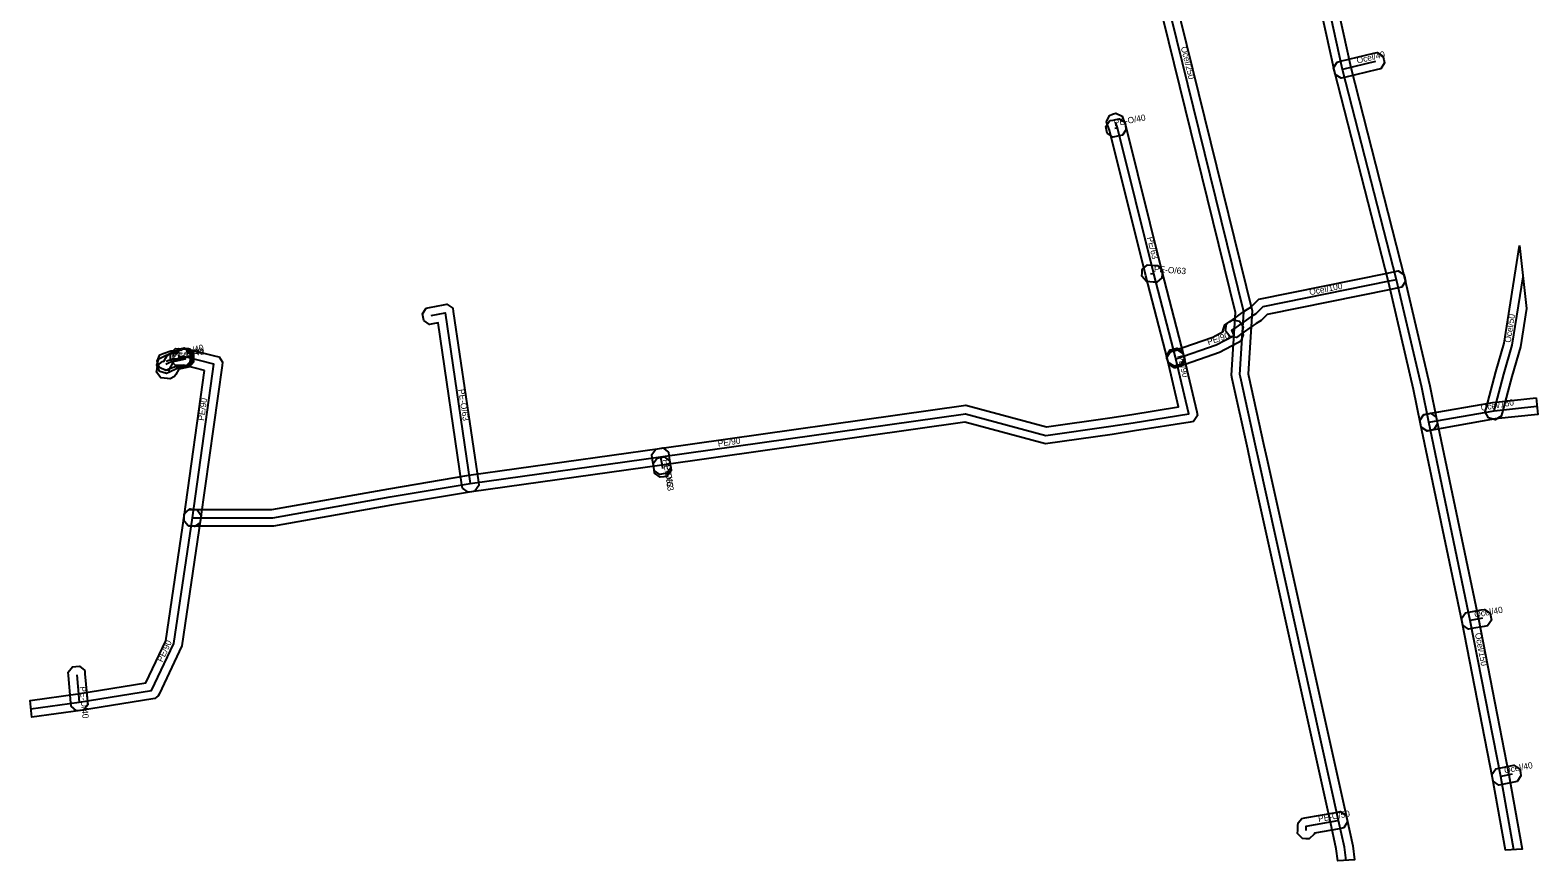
# Model space of a CAD drawing. Extents: x -697438 to -697243, y -1038718 to -1038521.
# Drawn here: x -697423.8 to -697243.1, y -1038717.8 to -1038618.2 of the extents above; entities that cross this region are included whole.
import ezdxf

# ---------------------------------------------------------------- set-up
doc = ezdxf.new("R2010")
doc.units = 0
for name, color, linetype in [('1', 7, 'Continuous'), ('14', 7, 'Continuous'), ('20', 7, 'Continuous'), ('24', 7, 'Continuous'), ('30', 7, 'Continuous')]:
    doc.layers.add(name, color=color, linetype=linetype)

msp = doc.modelspace()

# ---------------------------------------------------------------- linework, layer by layer
at = {"layer": '1'}
for points in [[(-697277.05, -1038570.41), (-697265.56, -1038622.68), (-697259.09, -1038647.89), (-697256.08, -1038660.84), (-697255.23, -1038665), (-697255.14, -1038665.4), (-697255.6, -1038666.09), (-697256.01, -1038666.18), (-697256.41, -1038666.26), (-697257.1, -1038665.8), (-697257.19, -1038665.4), (-697258.03, -1038661.27), (-697261.03, -1038648.37), (-697267.51, -1038623.15), (-697278.99, -1038570.88)], [(-697288.78, -1038605.48), (-697277.36, -1038651.87), (-697277.85, -1038659.42), (-697277.81, -1038659.59), (-697275.95, -1038667.99), (-697275.6, -1038669.55), (-697266.04, -1038712.7), (-697265.31, -1038715.98), (-697265.11, -1038717.64), (-697267.11, -1038717.76), (-697267.28, -1038716.31), (-697267.99, -1038713.14), (-697277.56, -1038669.98), (-697277.9, -1038668.43), (-697279.76, -1038660.02), (-697279.86, -1038659.57), (-697279.38, -1038652.05), (-697290.72, -1038605.96)]]:
    msp.add_lwpolyline(points, dxfattribs=at)
for points in [[(-697261.93, -1038622.84), (-697262.33, -1038622.94), (-697266.3, -1038623.89), (-697266.7, -1038623.98), (-697267.41, -1038623.55), (-697267.51, -1038623.15), (-697267.6, -1038622.74), (-697267.17, -1038622.04), (-697266.77, -1038621.94), (-697262.8, -1038620.99), (-697262.4, -1038620.9), (-697261.69, -1038621.33), (-697261.59, -1038621.73), (-697261.5, -1038622.14)], [(-697294.42, -1038629.06), (-697294.01, -1038628.99), (-697293.69, -1038628.93), (-697293.29, -1038628.85), (-697292.6, -1038629.32), (-697292.53, -1038629.73), (-697292.45, -1038630.13), (-697292.92, -1038630.82), (-697293.33, -1038630.89), (-697293.65, -1038630.95), (-697294.05, -1038631.03), (-697294.74, -1038630.56), (-697294.81, -1038630.15), (-697294.89, -1038629.75)], [(-697287.42, -1038658.06), (-697287.53, -1038657.66), (-697290.12, -1038647.66), (-697294.47, -1038630.2), (-697294.69, -1038629.58), (-697294.83, -1038629.19), (-697294.48, -1038628.44), (-697294.09, -1038628.3), (-697293.7, -1038628.16), (-697292.95, -1038628.51), (-697292.81, -1038628.9), (-697292.55, -1038629.62), (-697288.18, -1038647.16), (-697285.59, -1038657.16), (-697285.49, -1038657.56), (-697285.91, -1038658.27), (-697286.31, -1038658.37), (-697286.71, -1038658.48)], [(-697245.31, -1038644.01), (-697244.49, -1038651.59), (-697245.22, -1038656.18), (-697246.23, -1038659.71), (-697247.42, -1038664.08), (-697247.52, -1038664.48), (-697248.24, -1038664.9), (-697248.64, -1038664.79), (-697249.04, -1038664.68), (-697249.45, -1038663.96), (-697249.34, -1038663.56), (-697248.16, -1038659.17), (-697247.18, -1038655.74)], [(-697289.91, -1038646.35), (-697289.5, -1038646.38), (-697289.08, -1038646.41), (-697288.67, -1038646.44), (-697288.12, -1038647.07), (-697288.15, -1038647.48), (-697288.18, -1038647.89), (-697288.81, -1038648.44), (-697289.22, -1038648.41), (-697289.64, -1038648.38), (-697290.05, -1038648.35), (-697290.6, -1038647.72), (-697290.57, -1038647.31), (-697290.54, -1038646.9)], [(-697259.44, -1038649.02), (-697259.85, -1038649.11), (-697260.73, -1038649.3), (-697275.57, -1038652.29), (-697276.29, -1038653.03), (-697276.88, -1038653.37), (-697277.24, -1038653.6), (-697278.72, -1038654.66), (-697278.91, -1038654.8), (-697279.24, -1038655.04), (-697280.06, -1038654.92), (-697280.31, -1038654.58), (-697280.55, -1038654.25), (-697280.43, -1038653.43), (-697280.09, -1038653.19), (-697279.9, -1038653.04), (-697278.36, -1038651.94), (-697277.92, -1038651.65), (-697277.52, -1038651.43), (-697276.57, -1038650.45), (-697261.14, -1038647.34), (-697260.27, -1038647.15), (-697259.87, -1038647.07), (-697259.17, -1038647.51), (-697259.08, -1038647.92), (-697258.99, -1038648.32)], [(-697376.36, -1038651.53), (-697375.95, -1038651.45), (-697374.3, -1038651.12), (-697373.87, -1038651.04), (-697373.52, -1038651.28), (-697373.17, -1038651.53), (-697373.11, -1038651.95), (-697370.1, -1038672.39), (-697370.04, -1038672.8), (-697370.53, -1038673.47), (-697370.94, -1038673.53), (-697371.35, -1038673.59), (-697372.02, -1038673.1), (-697372.08, -1038672.69), (-697374.94, -1038653.29), (-697375.57, -1038653.41), (-697375.97, -1038653.49), (-697376.66, -1038653.03), (-697376.74, -1038652.62), (-697376.82, -1038652.22)], [(-697282.07, -1038655), (-697280.83, -1038654.35), (-697280.88, -1038654.26), (-697280.66, -1038653.54), (-697280.34, -1038653.34), (-697280.03, -1038653.14), (-697279.68, -1038652.92), (-697278.88, -1038653.11), (-697278.65, -1038653.46), (-697278.43, -1038653.81), (-697278.58, -1038654.47), (-697278.45, -1038654.75), (-697278.71, -1038655.5), (-697279.07, -1038655.69), (-697281.27, -1038656.84), (-697286.18, -1038658.55), (-697286.57, -1038658.68), (-697287.32, -1038658.32), (-697287.45, -1038657.93), (-697287.59, -1038657.54), (-697287.23, -1038656.79), (-697286.84, -1038656.66)], [(-697407.91, -1038657.9), (-697407.79, -1038657.91), (-697407.55, -1038657.47), (-697407.44, -1038657.28), (-697407.09, -1038657.02), (-697406.87, -1038656.97), (-697406.12, -1038656.82), (-697405.68, -1038656.38), (-697405.27, -1038656.38), (-697404.86, -1038656.38), (-697404.27, -1038656.97), (-697404.27, -1038657.38), (-697404.27, -1038657.66), (-697404.27, -1038658.02), (-697404.72, -1038658.57), (-697405.07, -1038658.64), (-697406.02, -1038658.84), (-697406.36, -1038659.47), (-697406.51, -1038659.74), (-697407.06, -1038660.02), (-697407.37, -1038659.98), (-697407.75, -1038659.93), (-697408.16, -1038659.88), (-697408.67, -1038659.22), (-697408.62, -1038658.81), (-697408.56, -1038658.4)], [(-697406.94, -1038656.87), (-697406.25, -1038656.68), (-697406.15, -1038656.51), (-697405.76, -1038656.4), (-697405.36, -1038656.29), (-697404.63, -1038656.69), (-697404.52, -1038657.09), (-697404.48, -1038657.22), (-697404.36, -1038657.63), (-697404.57, -1038657.99), (-697404.77, -1038658.35), (-697405.18, -1038658.46), (-697406.22, -1038658.75), (-697407.13, -1038659.2), (-697407.5, -1038659.38), (-697408.29, -1038659.12), (-697408.47, -1038658.75), (-697408.65, -1038658.38), (-697408.39, -1038657.59), (-697408.02, -1038657.41)], [(-697406.96, -1038656.64), (-697406.25, -1038656.59), (-697406.01, -1038656.38), (-697405.59, -1038656.4), (-697405.18, -1038656.43), (-697404.64, -1038657.05), (-697404.66, -1038657.47), (-697404.67, -1038657.62), (-697404.7, -1038657.99), (-697405.22, -1038658.52), (-697405.6, -1038658.55), (-697406.54, -1038658.62), (-697407.2, -1038658.86), (-697407.58, -1038659), (-697408.34, -1038658.66), (-697408.48, -1038658.27), (-697408.62, -1038657.88), (-697408.28, -1038657.12), (-697407.89, -1038656.98)], [(-697402.92, -1038659), (-697405.42, -1038658.37), (-697405.56, -1038658.4), (-697406.04, -1038658.39), (-697406.45, -1038658.38), (-697407.02, -1038657.78), (-697407.01, -1038657.36), (-697407, -1038656.95), (-697406.4, -1038656.38), (-697405.98, -1038656.39), (-697405.76, -1038656.4), (-697405.54, -1038656.35), (-697405.1, -1038656.39), (-697401.56, -1038657.28), (-697401.19, -1038657.37), (-697400.76, -1038658.01), (-697400.81, -1038658.39), (-697403.4, -1038676.79), (-697403.46, -1038677.2), (-697404.12, -1038677.7), (-697404.53, -1038677.64), (-697404.94, -1038677.58), (-697405.44, -1038676.92), (-697405.38, -1038676.51)], [(-697404.8, -1038675.65), (-697404.39, -1038675.65), (-697394.85, -1038675.66), (-697380.86, -1038673.17), (-697371.24, -1038671.55), (-697348.41, -1038668.35), (-697311.68, -1038663.17), (-697302.03, -1038665.77), (-697294.44, -1038664.68), (-697291.8, -1038664.27), (-697286.19, -1038663.37), (-697287.48, -1038657.83), (-697287.58, -1038657.43), (-697287.14, -1038656.72), (-697286.74, -1038656.63), (-697286.33, -1038656.53), (-697285.63, -1038656.97), (-697285.54, -1038657.37), (-697284, -1038663.96), (-697283.9, -1038664.39), (-697284.14, -1038664.75), (-697284.38, -1038665.11), (-697284.81, -1038665.18), (-697291.48, -1038666.25), (-697294.14, -1038666.66), (-697302.15, -1038667.81), (-697311.8, -1038665.21), (-697348.13, -1038670.33), (-697370.94, -1038673.53), (-697380.52, -1038675.14), (-697394.67, -1038677.66), (-697404.39, -1038677.65), (-697404.81, -1038677.65), (-697405.39, -1038677.06), (-697405.39, -1038676.65), (-697405.39, -1038676.23)], [(-697287.38, -1038658.25), (-697287.48, -1038657.85), (-697287.53, -1038657.66), (-697287.63, -1038657.26), (-697287.21, -1038656.54), (-697286.81, -1038656.44), (-697286.41, -1038656.33), (-697285.7, -1038656.76), (-697285.59, -1038657.16), (-697285.54, -1038657.35), (-697285.44, -1038657.75), (-697285.86, -1038658.46), (-697286.26, -1038658.57), (-697286.66, -1038658.67)], [(-697243.34, -1038662.27), (-697243.13, -1038664.26), (-697248.24, -1038664.81), (-697256.03, -1038666.18), (-697256.44, -1038666.25), (-697257.12, -1038665.78), (-697257.19, -1038665.37), (-697257.26, -1038664.96), (-697256.79, -1038664.28), (-697256.38, -1038664.21), (-697248.52, -1038662.83)], [(-697246.6, -1038707.45), (-697245, -1038716.38), (-697247.01, -1038716.5), (-697248.56, -1038707.82), (-697252.2, -1038689.15), (-697257.19, -1038665.4), (-697257.27, -1038665), (-697256.82, -1038664.3), (-697256.41, -1038664.22), (-697256.01, -1038664.13), (-697255.31, -1038664.59), (-697255.23, -1038664.99), (-697250.24, -1038688.75)], [(-697347.34, -1038668.78), (-697347.28, -1038669.19), (-697347.11, -1038670.26), (-697347.05, -1038670.67), (-697347.54, -1038671.34), (-697347.95, -1038671.4), (-697348.36, -1038671.47), (-697349.03, -1038670.98), (-697349.09, -1038670.57), (-697349.26, -1038669.49), (-697349.32, -1038669.08), (-697348.83, -1038668.42), (-697348.42, -1038668.35), (-697348.01, -1038668.29)], [(-697347.18, -1038669.86), (-697347.11, -1038670.27), (-697347.06, -1038670.6), (-697347, -1038671.01), (-697347.49, -1038671.67), (-697347.9, -1038671.74), (-697348.31, -1038671.8), (-697348.98, -1038671.31), (-697349.04, -1038670.9), (-697349.09, -1038670.57), (-697349.15, -1038670.16), (-697348.66, -1038669.49), (-697348.25, -1038669.43), (-697347.84, -1038669.36)], [(-697417.8, -1038699.73), (-697423.63, -1038700.54), (-697423.83, -1038698.55), (-697418.1, -1038697.75), (-697409.95, -1038696.44), (-697407.58, -1038691.41), (-697405.38, -1038676.5), (-697405.32, -1038676.09), (-697404.65, -1038675.6), (-697404.24, -1038675.66), (-697403.83, -1038675.72), (-697403.34, -1038676.39), (-697403.4, -1038676.8), (-697405.64, -1038691.99), (-697408.37, -1038697.77), (-697408.47, -1038697.99), (-697408.87, -1038698.29), (-697409.11, -1038698.33)], [(-697249.16, -1038689.6), (-697249.57, -1038689.67), (-697251.05, -1038689.93), (-697251.45, -1038690), (-697252.13, -1038689.53), (-697252.2, -1038689.12), (-697252.28, -1038688.71), (-697251.8, -1038688.03), (-697251.39, -1038687.96), (-697249.92, -1038687.7), (-697249.51, -1038687.63), (-697248.83, -1038688.1), (-697248.76, -1038688.51), (-697248.69, -1038688.92)], [(-697417.29, -1038694.95), (-697417.26, -1038695.37), (-697416.95, -1038698.65), (-697416.92, -1038699.06), (-697417.45, -1038699.7), (-697417.86, -1038699.74), (-697418.27, -1038699.77), (-697418.91, -1038699.24), (-697418.95, -1038698.83), (-697419.25, -1038695.55), (-697419.29, -1038695.14), (-697418.76, -1038694.5), (-697418.34, -1038694.46), (-697417.93, -1038694.42)], [(-697245.61, -1038708.27), (-697246.02, -1038708.35), (-697247.39, -1038708.62), (-697247.8, -1038708.7), (-697248.48, -1038708.23), (-697248.56, -1038707.83), (-697248.64, -1038707.42), (-697248.18, -1038706.73), (-697247.77, -1038706.65), (-697246.4, -1038706.39), (-697245.99, -1038706.31), (-697245.3, -1038706.77), (-697245.22, -1038707.18), (-697245.15, -1038707.59)], [(-697266.9, -1038713.92), (-697269.91, -1038714.46), (-697269.92, -1038714.56), (-697270.53, -1038715.12), (-697270.94, -1038715.11), (-697271.35, -1038715.09), (-697271.92, -1038714.48), (-697271.9, -1038714.07), (-697271.88, -1038713.57), (-697271.86, -1038713.22), (-697271.4, -1038712.69), (-697271.06, -1038712.62), (-697267.3, -1038711.96), (-697267.24, -1038711.95), (-697266.84, -1038711.85), (-697266.13, -1038712.29), (-697266.04, -1038712.69), (-697265.94, -1038713.09), (-697266.38, -1038713.8), (-697266.78, -1038713.89)]]:
    msp.add_lwpolyline(points, close=True, dxfattribs=at)
at = {"layer": '14'}
for points in [[(-697256.21, -1038665.2), (-697257.05, -1038661.05), (-697260.06, -1038648.13), (-697266.53, -1038622.92), (-697278.02, -1038570.65), (-697282.22, -1038554.39), (-697284.15, -1038547.02), (-697289.99, -1038530.66), (-697290.44, -1038528.42), (-697291.42, -1038528.73), (-697294.07, -1038522.86)], [(-697262.57, -1038621.97), (-697266.53, -1038622.92)], [(-697286.56, -1038657.41), (-697289.15, -1038647.41), (-697293.51, -1038629.91), (-697293.75, -1038629.24)], [(-697293.83, -1038629.97), (-697293.51, -1038629.91)], [(-697289.57, -1038647.38), (-697289.15, -1038647.41)], [(-697260.06, -1038648.13), (-697260.93, -1038648.32), (-697276.07, -1038651.37), (-697276.91, -1038652.23), (-697277.4, -1038652.51), (-697277.8, -1038652.77), (-697279.31, -1038653.85), (-697279.5, -1038653.99)], [(-697248.38, -1038663.82), (-697247.2, -1038659.44), (-697246.2, -1038655.96), (-697244.9, -1038647.8)], [(-697375.76, -1038652.43), (-697374.1, -1038652.1), (-697371.09, -1038672.54)], [(-697286.51, -1038657.6), (-697281.67, -1038655.92), (-697279.53, -1038654.8), (-697279.81, -1038654.19), (-697279.5, -1038653.99)], [(-697405.27, -1038657.38), (-697405.27, -1038657.66), (-697406.67, -1038657.95), (-697407.24, -1038658.99), (-697407.62, -1038658.94)], [(-697405.48, -1038657.36), (-697405.44, -1038657.5), (-697406.58, -1038657.81), (-697407.57, -1038658.3)], [(-697405.66, -1038657.4), (-697405.67, -1038657.55), (-697406.75, -1038657.63), (-697407.54, -1038657.92)], [(-697404.39, -1038676.65), (-697401.8, -1038658.25), (-697405.27, -1038657.38), (-697405.48, -1038657.36), (-697405.66, -1038657.4), (-697406.01, -1038657.39)], [(-697404.39, -1038676.65), (-697394.76, -1038676.66), (-697380.69, -1038674.15), (-697371.09, -1038672.54), (-697348.27, -1038669.34), (-697311.74, -1038664.19), (-697302.09, -1038666.79), (-697294.29, -1038665.67), (-697291.64, -1038665.26), (-697284.97, -1038664.19), (-697286.51, -1038657.6)], [(-697286.51, -1038657.6), (-697286.56, -1038657.41)], [(-697256.21, -1038665.2), (-697248.38, -1038663.82), (-697243.24, -1038663.26)], [(-697246, -1038716.44), (-697247.58, -1038707.64), (-697251.22, -1038688.95), (-697256.21, -1038665.2)], [(-697348.27, -1038669.34), (-697348.1, -1038670.42)], [(-697348.1, -1038670.42), (-697348.05, -1038670.75)], [(-697423.73, -1038699.54), (-697417.95, -1038698.74), (-697409.27, -1038697.34), (-697406.61, -1038691.7), (-697404.39, -1038676.65)], [(-697249.75, -1038688.69), (-697251.22, -1038688.95)], [(-697418.25, -1038695.46), (-697417.95, -1038698.74)], [(-697246.21, -1038707.37), (-697247.58, -1038707.64)]]:
    msp.add_lwpolyline(points, dxfattribs=at)
at = {"layer": '24'}
for points in [[(-697266.11, -1038717.7), (-697266.3, -1038716.14), (-697267.01, -1038712.92), (-697276.58, -1038669.77), (-697276.93, -1038668.21), (-697278.78, -1038659.81), (-697278.85, -1038659.49), (-697278.37, -1038651.96), (-697289.75, -1038605.72), (-697291.38, -1038599.12), (-697301, -1038555.15), (-697302.95, -1038547.61), (-697305.23, -1038542.66), (-697307.86, -1038537.02), (-697307.83, -1038536.25), (-697307.81, -1038535.8), (-697307.41, -1038525.56), (-697308.26, -1038524.31)], [(-697270.9, -1038714.11), (-697270.88, -1038713.61), (-697267.1, -1038712.94), (-697267.01, -1038712.92)]]:
    msp.add_lwpolyline(points, dxfattribs=at)

# ---------------------------------------------------------------- texts
at = {"layer": '20'}
for s, rotation, p in [('Ocel/40', 13.4602, (-697264.75, -1038622.24)), ('PE-O/40', 10.6197, (-697293.87, -1038629.74)), ('PE/63', 283.99, (-697289.98, -1038643.08)), ('PE-O/63', 355.9144, (-697289.16, -1038647.2)), ('Ocel/100', 11.3929, (-697270.44, -1038649.99)), ('Ocel/50', 80.9388, (-697246.39, -1038655.71)), ('PE/90', 19.1423, (-697282.61, -1038655.98)), ('PE-O/40', 11.7029, (-697406.8, -1038657.74)), ('PE-O/40', 15.2126, (-697406.67, -1038657.58)), ('PE-O/40', 4.2364, (-697406.76, -1038657.42)), ('PE/90', 284.4524, (-697286.35, -1038657.25)), ('PE-O/63', 278.3772, (-697372.52, -1038661.28)), ('PE/90', 81.9876, (-697402.99, -1038665.06)), ('Ocel/150', 9.9566, (-697249.9, -1038663.85)), ('PE/90', 8.0247, (-697341.36, -1038668.14)), ('PE-O/63', 278.8222, (-697347.99, -1038669.68)), ('PE/63', 278.59, (-697347.88, -1038670.38)), ('Ocel/40', 10.0102, (-697250.68, -1038688.62)), ('Ocel/150', 281.0184, (-697250.67, -1038690.52)), ('PE/90', 64.75, (-697407.99, -1038694.01)), ('PE-O/40', 275.2385, (-697417.9, -1038696.9)), ('Ocel/40', 10.9968, (-697247.09, -1038707.3))]:
    msp.add_text(s, height=0.75, rotation=rotation, dxfattribs=at).set_placement(p)
at = {"layer": '30'}
for s, rotation, p in [('Ocel/250', 283.8244, (-697285.92, -1038620.28)), ('PE-O/50', 10.0512, (-697269.39, -1038713.11))]:
    msp.add_text(s, height=0.75, rotation=rotation, dxfattribs=at).set_placement(p)

doc.saveas('drawing.dxf')
